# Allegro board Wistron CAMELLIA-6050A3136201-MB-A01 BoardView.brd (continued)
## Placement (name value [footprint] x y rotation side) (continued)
Q4751  PJX138K  [SOT563_160X120X060_6_050_P3]  203.67 70.64 180 bottom
Q4752  PJX138K  [SOT563_160X120X060_6_050_P3]  219.27 38.52 180 top
Q4754  LES_LBSS84LT1G_SOT23_3P  [TSSOT23_292X130X111_3_095]  250.85 48.88 0 top
Q4755  LES_LBSS84LT1G_SOT23_3P  [TSSOT23_292X130X111_3_095]  251.46 44.29 270 top
Q4756  TOSHIBA_SSM3K15AMFV_3P  [SOT723_120X080X055_3_040_P3]  39.27 35.63 270 bottom
Q4921  TOSHIBA_SSM3K15AMFV_3P_NP  [SOT723_120X080X055_3_040_NP]  107.97 43.37 0 top
Q7000  PJX138K  [SOT563_160X120X060_6_050_P3]  160.68 97.6 0 bottom
Q7001  PJS6416_6P  [SOT23_290X160X115_6_095]  199.42 91.02 270 bottom
Q7002  PJX138K  [SOT563_160X120X060_6_050_P3]  210.72 79.95 180 bottom
Q7003  PJX138K  [SOT563_160X120X060_6_050_P3]  211.99 89.35 180 bottom
Q7004  LN2312LT1G  [SOT23_290X130X110_3_095_P2]  214.78 88.97 0 bottom
Q7005  PJX138K  [SOT563_160X120X060_6_050_P3]  195.44 91.78 180 bottom
Q7006  TOSHIBA_SSM3K15AMFV_3P  [SOT723_120X080X055_3_040_P3]  216.05 91 90 top
Q7011  TOSHIBA_SSM3K15AMFV_3P  [SOT723_120X080X055_3_040_P3]  210.33 75.12 270 bottom
Q7151  ALPHA_AO6424L_TSOP_6P  [TSOP_290X160X125_6_095]  163.47 87.82 180 bottom
Q7153  ALPHA_AO6424L_TSOP_6P  [TSOP_290X160X125_6_095]  161.33 92.26 180 bottom
Q7154  LN2312LT1G  [SOT23_290X130X110_3_095_P2]  206.78 77.15 270 bottom
Q7159  EXCELLIANCE_MOS_EMB32N03K  [TSOT23_290X160X110_6_095]  167.03 42.99 0 top
Q7300  PJX138K  [SOT563_160X120X060_6_050_P3]  197.13 67.12 0 bottom
Q7306  PJX138K  [SOT563_160X120X060_6_050_P3]  211.05 77.28 0 bottom
Q7307  PJX138K  [SOT563_160X120X060_6_050_P3]  159.64 88.84 90 bottom
Q60000  AON6380  [MOSFET_500X600X100_8_127]  173.73 105.92 0 bottom
Q60001  AON6380  [MOSFET_500X600X100_8_127]  174.63 112.56 270 bottom
Q60002  AOS_AONR36368  [MOSFET_300X300X080_8_065]  157.12 114.2 0 bottom
Q60003  AOS_AONR36368  [MOSFET_300X300X080_8_065]  154.81 110.43 270 bottom
Q60010  SM3335PSQGC_TRG  [MOSFET_300X300X100_8_065]  252.12 96.15 180 top
Q60012  EMC_EMB07N03V  [MOSFET_300X300X090_8_065]  110.51 112.33 90 bottom
Q60032  L2N7002SWT1G  [SC70_200X125X100_3_065]  256.19 98.99 90 top
Q60033  LES_LBSS84LT1G_SOT23_3P  [TSSOT23_292X130X111_3_095]  248.46 97.68 90 top
Q60034  LES_LBSS84LT1G_SOT23_3P  [TSSOT23_292X130X111_3_095]  190.37 106.8 0 bottom
Q60035  L2N7002SWT1G  [SC70_200X125X100_3_065]  183.03 113.98 0 top
Q68000  YEL_LMBT3906LT1G_SOT23_3P  [TSSOT23_292X130X111_3_095]  209.55 115.97 90 bottom
Q68051  LMBT3904LT1G  [TSSOT23_292X130X111_3_096]  211.24 112.72 90 bottom
Q68054  L2N7002SWT1G  [SC70_200X125X100_3_065]  181 108.73 180 top
Q68098  L2N7002SWT1G  [SC70_200X125X100_3_065]  212.59 110.27 180 bottom
Q68100  SM3335PSQGC_TRG  [MOSFET_300X300X100_8_065]  252.5 91.94 90 top
Q68101  SM3335PSQGC_TRG  [MOSFET_300X300X100_8_065]  252.8 37.49 0 top
Q68102  NXP_PMBT3906YS_TSOT363_6P  [TSOT363_200X125X110_6_065_3]  243.99 28.64 270 top
Q68103  LES_LBSS84LT1G_SOT23_3P  [TSSOT23_292X130X111_3_095]  260.47 98.24 90 top
Q68104  LES_LBSS84LT1G_SOT23_3P  [TSSOT23_292X130X111_3_095]  254 41.19 180 top
Q68105  NXP_PMBT3906YS_TSOT363_6P  [TSOT363_200X125X110_6_065_3]  254.33 44.74 180 top
Q68106  SM3335PSQGC_TRG  [MOSFET_300X300X100_8_065]  266.11 83.15 270 top
Q68107  NXP_PMBT3906YS_TSOT363_6P  [TSOT363_200X125X110_6_065_3]  260.47 86.48 90 top
Q68108  LES_LBSS84LT1G_SOT23_3P  [TSSOT23_292X130X111_3_095]  254.28 84.9 90 top
Q68120  YEL_LMBT3906LT1G_SOT23_3P  [TSSOT23_292X130X111_3_095]  206.17 116.14 90 bottom
Q68121  YEL_LMBT3906LT1G_SOT23_3P  [TSSOT23_292X130X111_3_095]  206.19 112.84 90 bottom
R100  47_5%_1  [RSC_060X030X030_2]  241.37 30.88 180 top
R101  100K_5%_1  [RSC_060X030X030_2]  240.03 30.27 180 top
R103  100K_5%_1  [RSC_060X030X030_2]  240.03 29.66 180 top
R129  470K_1%_1  [RSC_060X030X030_2]  248.51 42.94 180 top
R200  short_0603_25  [RSC_160X080X080_2_25_SHORT]  55.44 10.38 270 bottom
R300  300_5%_1  [RSC_060X030X026_2]  246.99 40.07 180 top
R301  short_0201_5  [RSC_060X030X030_2_5_SHORT]  222.75 42.53 0 top
R302  300_5%_1  [RSC_060X030X026_2]  246.35 35.85 180 top
R303  100K_5%_1  [RSC_060X030X030_2]  242.39 50.87 0 bottom
R304  33_5%_1  [RSC_060X030X030_2]  221.33 36.01 180 top
R305  33_5%_1  [RSC_060X030X030_2]  221.48 36.62 180 top
R306  2.2K_5%_1  [RSC_060X030X030_2]  231.83 38.99 180 top
R307  2.2K_5%_1  [RSC_060X030X030_2]  231.82 39.61 180 top
R308  short_0201_5  [RSC_060X030X030_2_5_SHORT]  251.25 33.39 0 bottom
R309  34K_1%_2  [RSC_100X050X040_2]  248.11 36.84 0 top
R310  2.2K_5%_1  [RSC_060X030X030_2]  232.42 49.5 90 top
R311  2.2K_5%_1  [RSC_060X030X030_2]  233.04 49.37 90 top
R312  22_5%_1  [RSC_060X030X030_2]  216.13 47.94 270 top
R313  22_5%_1  [RSC_060X030X030_2]  224.63 47.94 270 top
R314  22_5%_1  [RSC_060X030X030_2]  222.75 47.94 270 top
R315  100K_5%_1  [RSC_060X030X030_2]  246.99 42.61 0 top
R316  4.7_5%_1  [RSC_060X030X030_2]  229.61 42.03 270 top
R317  100K_5%_1  [RSC_060X030X030_2]  250.72 46.47 90 top
R318  10K_5%_1  [RSC_060X030X030_2]  242.03 33.44 180 top
R319  short_0201_5  [RSC_060X030X030_2_5_SHORT]  253.62 31.82 0 bottom
R320  100K_5%_1  [RSC_060X030X030_2]  241.14 29.66 180 top
R321  20K_5%_1  [RSC_060X030X030_2]  242.21 47.61 180 top
R322  100K_5%_1  [RSC_060X030X030_2]  240.15 50.51 0 bottom
R323  short_0201_5  [RSC_060X030X030_2_5_SHORT]  253.62 32.42 0 bottom
R324  100K_5%_1  [RSC_060X030X030_2]  241.73 49.29 90 top
R325  10K_5%_1  [RSC_060X030X030_2]  249.86 46.27 0 top
R326  10K_5%_1  [RSC_060X030X030_2]  223.03 40.58 180 top
R327  470K_1%_2  [RSC_100X050X040_2]  238.68 25.36 180 top
R328  43_5%_1  [RSC_060X030X030_2]  237.61 49.37 90 top
R329  10K_5%_1  [RSC_060X030X030_2]  234.26 49.37 90 top
R330  short_0201_10  [RSC_060X030X030_2_10_SHORT]  233.65 49.37 90 top
R331  4.7K_5%_1  [RSC_060X030X030_2]  218.97 47.94 270 top
R332  short_0201_5  [RSC_060X030X030_2_5_SHORT]  239.82 48.6 270 top
R333  short_0201_5  [RSC_060X030X030_2_5_SHORT]  226.97 37.66 270 top
R334  100K_5%_1  [RSC_060X030X030_2]  241.09 49.29 90 top
R335  short_0201_5  [RSC_060X030X030_2_5_SHORT]  260.93 31.76 90 bottom
R336  15_5%_1  [RSC_060X030X030_2]  260.3 31.76 90 bottom
R337  15_5%_1  [RSC_060X030X030_2]  259.66 31.99 90 bottom
R338  15_5%_1  [RSC_060X030X030_2]  259.03 32.32 90 bottom
R339  15_5%_1  [RSC_060X030X030_2]  258.39 32.32 90 bottom
R340  short_0201_5  [RSC_060X030X030_2_5_SHORT]  252.5 32.53 0 bottom
R341  100K_5%_1  [RSC_060X030X030_2]  242.8 52.82 270 bottom
R342  10K_5%_1  [RSC_060X030X030_2]  249.86 46.98 180 top
R343  short_0402_15  [RSC_100X050X040_2_15_SHORT]  50.06 16.32 270 bottom
R344  3.3K_5%_1  [RSC_060X030X026_2]  230.7 26.41 315 top
R345  0_5%_1  [RSC_060X030X030_2]  229.89 27.37 135 top
R346  3.3K_5%_1  [RSC_060X030X026_2]  221.13 34.74 225 top
R347  short_0402_15  [RSC_100X050X040_2_15_SHORT]  226.49 39.44 0 top
R348  1K_5%_1  [RSC_060X030X030_2]  230.53 38.01 90 top
R349  1K_5%_1  [RSC_060X030X030_2]  244.47 47.84 90 top
R350  0_5%_1  [RSC_060X030X030_2]  239.14 30.88 180 top
R351  100K_5%_1  [RSC_060X030X030_2]  129.79 4.05 90 bottom
R352  100K_5%_1  [RSC_060X030X030_2]  240.48 34.06 270 top
R353  short_0201_10  [RSC_060X030X030_2_10_SHORT]  248.51 43.58 180 top
R354  10K_5%_1  [RSC_060X030X030_2]  240.1 49.9 0 bottom
R355  4.7K_5%_1  [RSC_060X030X030_2]  229.77 25.47 135 top
R356  1K_5%_1  [RSC_060X030X030_2]  236.04 31.05 0 top
R357  100K_5%_1  [RSC_060X030X030_2]  240.05 28.26 180 top
R358  short_0201_5  [RSC_060X030X030_2_5_SHORT]  250.97 32.58 0 bottom
R359  short_0402_15  [RSC_100X050X040_2_15_SHORT]  249.32 41.82 270 top
R360  short_0201_10  [RSC_060X030X030_2_10_SHORT]  240.05 53.91 180 bottom
R361  short_0201_10  [RSC_060X030X030_2_10_SHORT]  241.27 50.56 180 bottom
R362  short_0402_15  [RSC_100X050X040_2_15_SHORT]  48.26 16.32 270 bottom
R364  470_5%_1  [RSC_060X030X030_2]  47.49 16.07 270 bottom
R365  470_5%_1  [RSC_060X030X030_2]  46.89 16.07 270 bottom
R366  200_5%_2  [RSC_100X050X040_2]  45.74 16.07 180 bottom
R367  22_5%_1  [RSC_060X030X030_2]  225.85 47.94 90 top
R368  100K_5%_1  [RSC_060X030X030_2]  219.63 47.94 270 top
R369  100K_5%_1  [RSC_060X030X030_2]  223.36 47.94 270 top
R370  0_5%_1  [RSC_060X030X030_2]  222.15 47.94 270 top
R371  200_5%_2  [RSC_100X050X040_2]  51.2 19.37 270 bottom
R372  100K_5%_1  [RSC_060X030X030_2]  48.59 17.72 270 bottom
R373  short_0603_25  [RSC_160X080X080_2_25_SHORT]  223.57 60.31 270 bottom
R374  short_0201_5  [RSC_060X030X030_2_5_SHORT]  222.75 41.87 0 top
R375  1K_5%_1  [RSC_060X030X030_2]  235.66 29.45 0 top
R376  100K_5%_1  [RSC_060X030X030_2]  46.89 17.21 90 bottom
R377  short_0201_5  [RSC_060X030X030_2_5_SHORT]  226.36 37.66 90 top
R378  100K_5%_1  [RSC_060X030X030_2]  236.04 31.66 0 top
R379  2.2_5%_2  [RSC_100X050X040_2]  229.79 40.81 0 top
R380  1K_5%_1  [RSC_060X030X030_2]  232.2 35.27 180 top
R381  2.2_5%_3  [RSC_160X080X080_2]  246.46 38.57 90 top
R382  1K_5%_1  [RSC_060X030X030_2]  132.36 4.38 0 bottom
R383  0_5%_1  [RSC_060X030X030_2]  238.93 47.61 0 top
R384  short_0402_15  [RSC_100X050X040_2_15_SHORT]  247.83 37.76 180 top
R385  100K_5%_1  [RSC_060X030X030_2]  241.2 28.26 180 top
R386  0_5%_1  [RSC_060X030X030_2]  239.01 48.48 270 top
R387  100K_5%_1  [RSC_060X030X030_2]  224.81 38.55 0 top
R388  200_5%_2  [RSC_100X050X040_2]  49.17 16.32 270 bottom
R389  100K_5%_1  [RSC_060X030X030_2]  46.25 17.21 90 bottom
R390  33_5%_1  [RSC_060X030X030_2]  230.27 25.97 135 top
R391  10K_5%_1  [RSC_060X030X030_2]  231.8 49.49 90 top
R392  200_5%_2  [RSC_100X050X040_2]  44.09 16.07 0 bottom
R393  short_0402_15  [RSC_100X050X040_2_15_SHORT]  44.09 16.96 180 bottom
R394  10K_5%_1  [RSC_060X030X030_2]  231.19 49.49 90 top
R395  10_5%_1  [RSC_060X030X030_2]  257.63 33.11 90 bottom
R396  100K_5%_1  [RSC_060X030X030_2]  237 49.37 90 top
R397  2.2K_5%_1  [RSC_060X030X030_2]  231.75 38.01 90 top
R398  short_0201_5  [RSC_060X030X030_2_5_SHORT]  240.26 31.54 180 top
R399  200K_5%_1  [RSC_060X030X030_2]  46.76 21.02 270 bottom
R400  10K_5%_2  [RSC_100X050X040_2]  216.81 5.15 0 bottom
R401  short_0201_10  [RSC_060X030X030_2_10_SHORT]  108.38 7.41 0 top
R402  200K_5%_1  [RSC_060X030X030_2]  47.65 21.05 270 bottom
R403  100K_5%_2  [RSC_100X050X040_2]  49.55 21.68 270 bottom
R404  short_0402_15  [RSC_100X050X040_2_15_SHORT]  50.95 21.27 0 bottom
R405  short_0805_50  [RSC_200X125X115_2_50_SHORT]  228.09 38.5 90 top
R406  100K_5%_1  [RSC_060X030X030_2]  223.03 41.21 180 top
R407  short_0402_15  [RSC_100X050X040_2_15_SHORT]  215.54 5.02 90 bottom
R408  0_5%_1  [RSC_060X030X030_2]  47.39 21.91 0 bottom
R409  short_0201_10  [RSC_060X030X030_2_10_SHORT]  47.39 22.54 0 bottom
R410  short_0201_10  [RSC_060X030X030_2_10_SHORT]  45.49 21.02 270 bottom
R411  0_5%_1  [RSC_060X030X030_2]  46.12 21.02 270 bottom
R413  560_5%_2  [RSC_100X050X040_2]  269.39 100.65 270 top
R415  short_0201_5  [RSC_060X030X030_2_5_SHORT]  238.25 29.78 90 top
R417  10K_5%_1  [RSC_060X030X030_2]  250.75 34.43 90 bottom
R418  100K_5%_1  [RSC_060X030X030_2]  224.02 47.94 270 top
R419  33_5%_1  [RSC_060X030X030_2]  230.4 27.88 315 top
R420  short_0201_5  [RSC_060X030X030_2_5_SHORT]  229.61 45.02 0 top
R421  33_5%_1  [RSC_060X030X030_2]  219.81 35.4 135 top
R422  22_5%_1  [RSC_060X030X030_2]  220.24 47.94 270 top
R423  1M_5%_1  [RSC_060X030X030_2]  259.72 3.09 0 bottom
R424  100_5%_2  [RSC_100X050X040_2]  231.29 57.22 180 top
R425  22_5%_1  [RSC_060X030X030_2]  226.46 47.94 270 top
R426  10K_5%_1  [RSC_060X030X030_2]  239.42 33.97 270 top
R428  0_5%_1  [RSC_060X030X030_2]  25.83 19.5 0 top
R430  100K_1%_1  [RSC_060X030X030_2]  244.12 33.16 270 top
R431  806K_1%_2  [RSC_100X050X040_2]  243.23 34.81 0 top
R432  100K_1%_1  [RSC_060X030X030_2]  242.9 33.16 270 top
R433  short_0201_10  [RSC_060X030X030_2_10_SHORT]  231.04 42.18 90 top
R434  short_0201_10  [RSC_060X030X030_2_10_SHORT]  223.92 40.07 270 top
R435  560_5%_2  [RSC_100X050X040_2]  268.5 100.9 270 top
R439  4.7_5%_1  [RSC_060X030X030_2]  228.5 45.02 0 top
R440  4.7_5%_1  [RSC_060X030X030_2]  229.61 43.14 270 top
R441  4.7_5%_1  [RSC_060X030X030_2]  223.52 43.58 90 top
R442  22_5%_1  [RSC_060X030X030_2]  218.34 47.94 270 top
R443  300_5%_1  [RSC_060X030X026_2]  246.99 40.71 180 top
R444  300_5%_1  [RSC_060X030X026_2]  245.43 35.19 90 top
R445  1M_5%_2  [RSC_100X050X040_2]  216.81 3.75 180 bottom
R449  22K_5%_2  [RSC_100X050X040_2]  237.64 28.77 0 top
R500  100K_5%_2  [RSC_100X050X040_2]  28.47 37.02 180 top
R501  100K_1%_2  [RSC_100X050X040_2]  17.57 34.4 270 top
R502  1K_5%_2  [RSC_100X050X040_2]  28.47 36.13 180 top
R503  short_0402_15  [RSC_100X050X040_2_15_SHORT]  16.68 34.4 270 top
R504  33_5%_1  [RSC_060X030X030_2]  26.97 37.98 0 top
R505  0_5%_1  [RSC_060X030X030_2]  26.97 37.12 0 top
R506  100K_5%_2  [RSC_100X050X040_2]  17.14 43.71 0 top
R507  1K_5%_1  [RSC_060X030X030_2]  17.75 45.91 270 top
R508  10K_5%_2  [RSC_100X050X040_2]  13.36 46.04 0 top
R509  short_0805_40_nsp  [RSC_200X125X115_2_40_SHORT_NSP]  8.79 44.77 90 top
R510  short_0805_40_nsp  [RSC_200X125X115_2_40_SHORT_NSP]  7.18 44.77 90 top
R511  2.2K_5%_2  [RSC_100X050X040_2]  22.96 46.01 180 top
R512  short_0805_50  [RSC_200X125X115_2_50_SHORT]  12.9 36.21 0 top
R513  Short_0805_50_NSP  [RSC_200X125X115_2_50_SHORT_NSP]  43.96 36.13 180 top
R514  short_0805_50  [RSC_200X125X115_2_50_SHORT]  28.47 45.66 180 top
R515  short_0201_10  [RSC_060X030X030_2_10_SHORT]  19.33 36.59 0 top
R516  100K_5%_2  [RSC_100X050X040_2]  26.67 35.78 0 top
R517  short_0402_15  [RSC_100X050X040_2_15_SHORT]  11.45 43.4 90 top
R518  100K_5%_2  [RSC_100X050X040_2]  13.24 44.79 90 top
R519  200K_5%_2  [RSC_100X050X040_2]  11.22 42.15 0 top
R520  short_0603_25  [RSC_160X080X080_2_25_SHORT]  14.86 43.88 0 top
R521  short_0603_25  [RSC_160X080X080_2_25_SHORT]  14.26 42.11 270 top
R550  short_0603_25  [RSC_160X080X080_2_25_SHORT]  5.93 40.26 180 top
R551  short_0603_25  [RSC_160X080X080_2_25_SHORT]  5.93 36.3 180 top
R566  short_0603_25  [RSC_160X080X080_2_25_SHORT]  5.93 37.44 180 top
R567  short_0603_25  [RSC_160X080X080_2_25_SHORT]  5.93 38.99 180 top
R906  51.1K_1%_2  [RSC_100X050X040_2]  245.41 37.43 270 top
R1000  10K_5%_2  [RSC_100X050X040_2]  236.39 28.08 270 top
R1001  100K_5%_2  [RSC_100X050X040_2]  236.39 26.46 270 top
R1002  10K_5%_2  [RSC_100X050X040_2]  140.53 5.91 180 top
R1003  10K_5%_2  [RSC_100X050X040_2]  140.53 7.76 180 top
R1004  100K_5%_2  [RSC_100X050X040_2]  140.53 6.8 0 top
R1005  short_0402_15  [RSC_100X050X040_2_15_SHORT]  140.53 8.65 0 top
R1006  short_0402_15  [RSC_100X050X040_2_15_SHORT]  135.53 8.32 270 top
R1007  10K_5%_1  [RSC_060X030X030_2]  215.16 47.77 0 top
R1008  1M_5%_1  [RSC_060X030X030_2]  262.69 8.31 180 bottom
R1009  10M_5%_1  [RSC_060X030X030_2]  260.82 3.09 0 bottom
R1010  short_0402_15  [RSC_100X050X040_2_15_SHORT]  239.95 26.63 90 top
R1011  short_0201_10  [RSC_060X030X030_2_10_SHORT]  24.15 7.61 270 bottom
R1012  100K_5%_1  [RSC_060X030X030_2]  237.18 26.41 90 top
R1013  short_0402_15  [RSC_100X050X040_2_15_SHORT]  134.74 9.59 0 top
R1014  10K_5%_2  [RSC_100X050X040_2]  215.29 102.3 90 bottom
R1015  220K_1%_2  [RSC_100X050X040_2]  214.02 102.81 180 bottom
R1016  110K_1%_2  [RSC_100X050X040_2]  214.02 101.92 0 bottom
R1017  10K_5%_2  [RSC_100X050X040_2]  214.3 98.11 0 bottom
R1018  100K_5%_1  [RSC_060X030X030_2]  246.53 46.17 0 top
R1019  10K_5%_1  [RSC_060X030X030_2]  221.89 58.23 270 top
R1021  10K_5%_2  [RSC_100X050X040_2]  134.29 8.68 180 top
R1300  100K_5%_1  [RSC_060X030X030_2]  188.82 70.8 180 top
R1301  10K_5%_2  [RSC_100X050X040_2]  54.86 22.34 0 bottom
R1302  150_1%_2  [RSC_100X050X040_2]  73.94 38.04 0 bottom
R1303  short_0402_15  [RSC_100X050X040_2_15_SHORT]  51.08 27.24 180 bottom
R1304  100K_5%_2  [RSC_100X050X040_2]  55.37 24.39 90 top
R1305  100K_5%_2  [RSC_100X050X040_2]  51.08 26.35 0 bottom
R1306  10K_5%_2  [RSC_100X050X040_2]  61.24 29.53 270 bottom
R1307  100K_5%_2  [RSC_100X050X040_2]  58.04 29.15 180 bottom
R1308  short_0402_15  [RSC_100X050X040_2_15_SHORT]  56.38 29.12 180 bottom
R1309  20K_5%_1  [RSC_060X030X030_2]  59.97 23.26 90 bottom
R1310  short_0201_5  [RSC_060X030X030_2_5_SHORT]  60.91 27.6 0 bottom
R1312  22_1%_1  [RSC_060X030X026_2]  193.32 60.47 90 bottom
R1313  22_1%_1  [RSC_060X030X026_2]  60.93 22.34 180 bottom
R1314  22_1%_1  [RSC_060X030X026_2]  61.19 23.26 270 bottom
R1315  short_0805_50  [RSC_200X125X115_2_50_SHORT]  59.69 35.24 0 bottom
R1316  22_1%_1  [RSC_060X030X026_2]  61.13 24.98 270 bottom
R1317  short_0402_15  [RSC_100X050X040_2_15_SHORT]  60.6 21.15 90 bottom
R1318  short_0201_10  [RSC_060X030X030_2_10_SHORT]  60.47 20.04 0 bottom
R1319  short_0201_10  [RSC_060X030X030_2_10_SHORT]  59.61 19.75 270 bottom
R1320  short_0201_10  [RSC_060X030X030_2_10_SHORT]  73.56 34.86 0 bottom
R1321  short_0201_10  [RSC_060X030X030_2_10_SHORT]  73.56 34.23 0 bottom
R1322  short_0201_10  [RSC_060X030X030_2_10_SHORT]  73.56 33.34 0 bottom
R1323  short_0201_10  [RSC_060X030X030_2_10_SHORT]  73.56 32.7 0 bottom
R1324  short_0201_10  [RSC_060X030X030_2_10_SHORT]  73.56 31.82 0 bottom
R1325  short_0201_10  [RSC_060X030X030_2_10_SHORT]  73.56 31.18 0 bottom
R1326  short_0201_10  [RSC_060X030X030_2_10_SHORT]  72.21 23.18 90 bottom
R1327  short_0201_10  [RSC_060X030X030_2_10_SHORT]  72.82 23.18 90 bottom
R1328  short_0201_10  [RSC_060X030X030_2_10_SHORT]  73.43 23 90 bottom
R1329  short_0201_10  [RSC_060X030X030_2_10_SHORT]  74.04 23 90 bottom
R1332  71.5K_1%_2  [RSC_100X050X040_2]  59.71 21.15 90 bottom
R1333  4.7K_5%_1  [RSC_060X030X030_2]  60.58 23.26 270 bottom
R1334  short_0201_10  [RSC_060X030X030_2_10_SHORT]  74.65 23 90 bottom
R1335  short_0201_10  [RSC_060X030X030_2_10_SHORT]  75.25 23 90 bottom
R1336  10K_5%_2  [RSC_100X050X040_2]  180.26 84.47 0 bottom
R1337  0_5%_2  [RSC_100X050X040_2]  60.6 33.97 0 bottom
R1338  short_0201_10  [RSC_060X030X030_2_10_SHORT]  74.34 26.84 0 bottom
R1339  short_0201_10  [RSC_060X030X030_2_10_SHORT]  74.34 26.23 0 bottom
R1342  100K_5%_2  [RSC_100X050X040_2]  49.81 35.12 270 bottom
R1343  220K_5%_2  [RSC_100X050X040_2]  52.73 31.18 90 bottom
R1344  4.7K_5%_1  [RSC_060X030X030_2]  193.32 62.17 90 bottom
R1345  20K_5%_1  [RSC_060X030X030_2]  193.95 62.17 270 bottom
R1346  100K_5%_2  [RSC_100X050X040_2]  60.86 30.8 0 bottom
R1347  short_0402_15  [RSC_100X050X040_2_15_SHORT]  53.21 22.34 0 bottom
R1349  short_0402_15  [RSC_100X050X040_2_15_SHORT]  51.08 29.66 0 bottom
R1351  short_0402_15  [RSC_100X050X040_2_15_SHORT]  51.78 24.44 90 bottom
R1400  100K_5%_1  [RSC_060X030X030_2]  197.76 50.74 90 bottom
R1401  20K_5%_1  [RSC_060X030X030_2]  208 62.07 90 bottom
R1402  0_5%_2  [RSC_100X050X040_2]  206.65 63.31 90 bottom
R1403  short_0805_50  [RSC_200X125X115_2_50_SHORT]  216.56 61.03 90 top
R1404  10K_5%_1  [RSC_060X030X030_2]  200.17 61.28 180 top
R1405  10_5%_1  [RSC_060X030X030_2]  201.83 63.44 90 bottom
R1406  10_5%_1  [RSC_060X030X030_2]  202.46 63.44 90 bottom
R1407  0_5%_2  [RSC_100X050X040_2]  205.76 63.31 90 bottom
R1408  100K_5%_1  [RSC_060X030X030_2]  205 52.9 180 top
R1409  0_5%_2  [RSC_100X050X040_2]  208.3 66.11 0 bottom
R1410  100K_5%_1  [RSC_060X030X030_2]  209.38 56.18 270 top
R1411  0_5%_1  [RSC_060X030X030_2]  210.02 56.19 90 top
R1412  short_0201_10  [RSC_060X030X030_2_10_SHORT]  213.64 55.82 180 top
R1413  0_5%_1  [RSC_060X030X030_2]  203.86 52.9 180 top
R1414  short_0201_10  [RSC_060X030X030_2_10_SHORT]  215.32 63.19 270 bottom
R1417  100K_5%_2  [RSC_100X050X040_2]  215.8 65.85 180 bottom
R1451  47K_5%_1  [RSC_060X030X030_2]  269.23 45.32 90 top
R1452  100K_5%_1  [RSC_060X030X030_2]  269.85 47.6 90 top
R1952  1K_5%_2  [RSC_100X050X040_2]  259.99 10.48 0 top
R1953  short_0805_50  [RSC_200X125X115_2_50_SHORT]  265.53 18.71 270 top
R1954  100K_5%_2  [RSC_100X050X040_2]  267.74 12.13 270 top
R2200  100K_5%_1  [RSC_060X030X030_2]  234.69 7.94 0 top
R2401  short_0402_15  [RSC_100X050X040_2_15_SHORT]  257.6 33.33 270 top
R2402  short_0402_15  [RSC_100X050X040_2_15_SHORT]  255.23 32.92 0 top
R2418  10K_5%_2  [RSC_100X050X040_2]  266.89 22.25 0 top
R2420  0_5%_2  [RSC_100X050X040_2]  255.23 30.99 0 top
R2421  100K_5%_2  [RSC_100X050X040_2]  262.23 20.69 270 top
R2422  100K_5%_2  [RSC_100X050X040_2]  263.8 33.21 90 bottom
R2423  100K_5%_2  [RSC_100X050X040_2]  249.55 26.51 180 top
R2424  100K_5%_2  [RSC_100X050X040_2]  249.55 27.42 180 top
R2425  100K_5%_2  [RSC_100X050X040_2]  249.56 24.67 180 top
R2427  0_5%_2  [RSC_100X050X040_2]  255.22 28.49 0 top
R2428  100K_5%_2  [RSC_100X050X040_2]  249.56 25.59 180 top
R2441  4.7K_5%_2  [RSC_100X050X040_2]  262.91 33.21 270 bottom
R2449  0_5%_2  [RSC_100X050X040_2]  266.89 23.17 0 top
R2456  short_0805_50  [RSC_200X125X115_2_50_SHORT]  261.77 18.86 180 top
R2457  1K_1%_2  [RSC_100X050X040_2]  250.9 21.93 0 top
R2458  1K_1%_2  [RSC_100X050X040_2]  250.9 22.85 180 top
R2463  51K_1%_2  [RSC_100X050X040_2]  255.77 20.83 180 top
R2464  357K_1%_2  [RSC_100X050X040_2]  257.83 20.78 0 top
R2465  76.8K_1%_2  [RSC_100X050X040_2]  257.83 19.88 0 top
R2466  127K_1%  [RSC_100X050X040_2]  255.77 19.93 180 top
R2469  short_0603_25  [RSC_160X080X080_2_25_SHORT]  269.36 33.49 0 top
R2500  17.8K_1%_2  [RSC_100X050X040_2]  25.88 27.12 270 top
R2501  33.2K_1%_2  [RSC_100X050X040_2]  25.88 25.47 270 top
R2502  10K_5%_2  [RSC_100X050X040_2]  27 31.18 90 top
R2503  0_5%_2  [RSC_100X050X040_2]  27.89 31.18 270 top
R2513  short_0201_5  [RSC_060X030X030_2_5_SHORT]  245.44 42.43 0 top
R2600  10K_5%_2  [RSC_100X050X040_2]  256.64 40.81 180 top
R2601  220K_5%_2  [RSC_100X050X040_2]  258.26 42.25 0 top
R2602  200K_5%_2  [RSC_100X050X040_2]  257.06 46.42 0 top
R2603  14.3K_1%_2  [RSC_100X050X040_2]  265.55 96.53 0 top
R2604  47K_5%_2  [RSC_100X050X040_2]  266.44 97.78 270 top
R2605  220K_1%_1  [RSC_060X030X026_2]  278.45 76.76 90 bottom
R2606  300K_5%_2  [RSC_100X050X040_2]  254.96 47.36 270 top
R2607  220K_1%_1  [RSC_060X030X026_2]  276.04 68.54 90 bottom
R2608  220K_1%_1  [RSC_060X030X026_2]  276.04 67.43 270 bottom
R2609  220K_1%_1  [RSC_060X030X026_2]  277.41 62.37 90 top
R2610  10K_5%_2  [RSC_100X050X040_2]  268.63 86.37 90 top
R2611  20K_1%_2  [RSC_100X050X040_2]  263.22 95.11 180 top
R2612  10K_5%_2  [RSC_100X050X040_2]  263.22 96.03 0 top
R2613  200K_5%_2  [RSC_100X050X040_2]  261.59 95.11 0 top
R2614  300K_5%_2  [RSC_100X050X040_2]  261.59 96.03 0 top
R2615  100K_5%_2  [RSC_100X050X040_2]  265.2 97.78 90 top
R2616  220K_1%_1  [RSC_060X030X026_2]  278.45 75.64 270 bottom
R2617  14.3K_1%_2  [RSC_100X050X040_2]  263.78 42.28 180 top
R2618  1M_5%_2  [RSC_100X050X040_2]  267.71 97.59 0 top
R2619  20K_1%_2  [RSC_100X050X040_2]  258.66 46.42 180 top
R2620  47K_5%_2  [RSC_100X050X040_2]  265.15 42.05 270 top
R2621  10K_5%_2  [RSC_100X050X040_2]  258.62 47.33 0 top
R2622  220K_1%_1  [RSC_060X030X026_2]  278.45 80.77 270 bottom
R2623  220K_1%_1  [RSC_060X030X026_2]  277.41 63.49 270 top
R2624  220K_1%_1  [RSC_060X030X026_2]  278.45 81.89 90 bottom
R2625  Short_0805_50_NSP  [RSC_200X125X115_2_50_SHORT_NSP]  260.91 44.16 0 top
R2626  short_0402_15  [RSC_100X050X040_2_15_SHORT]  259.69 34.99 270 top
R2627  100K_5%_2  [RSC_100X050X040_2]  258.06 49.09 90 top
R2628  1M_5%_2  [RSC_100X050X040_2]  267.79 40.43 90 top
R2629  220K_1%_1  [RSC_060X030X026_2]  278.15 75.64 90 top
R2630  220K_1%_1  [RSC_060X030X026_2]  278.15 76.76 270 top
R2631  220K_1%_1  [RSC_060X030X026_2]  278.15 80.77 90 top
R2632  220K_1%_1  [RSC_060X030X026_2]  278.15 81.89 270 top
R2633  100K_5%_2  [RSC_100X050X040_2]  256.69 33.16 270 top
R2634  100K_5%_2  [RSC_100X050X040_2]  253.22 32.92 180 top
R2635  220K_5%_2  [RSC_100X050X040_2]  269.54 86.37 90 top
R2638  Short_0805_50_NSP  [RSC_200X125X115_2_50_SHORT_NSP]  268.18 89.34 90 top
R2639  Short_0805_50_NSP  [RSC_200X125X115_2_50_SHORT_NSP]  269.81 89.34 90 top
R2640  220K_1%_1  [RSC_060X030X026_2]  276.65 63.49 90 bottom
R2641  220K_1%_1  [RSC_060X030X026_2]  276.65 62.37 270 bottom
R2642  220K_1%_1  [RSC_060X030X026_2]  276.04 67.43 90 top
R2643  220K_1%_1  [RSC_060X030X026_2]  276.04 68.54 270 top
R2647  Short_0805_50_NSP  [RSC_200X125X115_2_50_SHORT_NSP]  271.43 89.34 90 top
R2655  short_0402_15  [RSC_100X050X040_2_15_SHORT]  254.07 20.68 270 top
R2656  short_0402_15  [RSC_100X050X040_2_15_SHORT]  253.16 20.68 270 top
R2657  short_0402_15  [RSC_100X050X040_2_15_SHORT]  253.15 29.16 180 top
R2658  short_0402_15  [RSC_100X050X040_2_15_SHORT]  253.15 30.08 180 top
R2660  short_0402_15  [RSC_100X050X040_2_15_SHORT]  258.44 35.63 0 top
R2669  Short_0805_50_NSP  [RSC_200X125X115_2_50_SHORT_NSP]  260.91 42.56 0 top
R2671  Short_0805_50_NSP  [RSC_200X125X115_2_50_SHORT_NSP]  260.91 45.79 0 top
R2684  short_0402_15  [RSC_100X050X040_2_15_SHORT]  257.2 34.94 270 top
R2700  100_1%_1  [RSC_060X030X030_2]  253.34 65.95 0 bottom
R2701  100K_5%_1  [RSC_060X030X030_2]  247.34 74.72 270 top
R2702  short_0201_5  [RSC_060X030X030_2_5_SHORT]  253.54 73.7 270 top
R2703  0_5%_1  [RSC_060X030X030_2]  250.36 74.18 0 top
R2704  short_0201_5  [RSC_060X030X030_2_5_SHORT]  252.9 73.7 270 top
R2705  0_5%_1  [RSC_060X030X030_2]  247.85 70.65 90 top
R2706  100K_5%_1  [RSC_060X030X030_2]  246.15 71.39 0 top
R2708  3.01K_1%_1  [RSC_060X030X030_2]  257.83 60.9 90 bottom
R2709  short_0201_10  [RSC_060X030X030_2_10_SHORT]  248.41 76.27 180 top
R2710  10K_5%_1  [RSC_060X030X030_2]  253.31 71.97 270 top
R2711  10K_5%_1  [RSC_060X030X030_2]  250.06 68.87 180 top
R2712  10K_5%_1  [RSC_060X030X030_2]  247.16 73.6 90 top
R2713  2.2_1%_1  [RSC_060X030X026_2]  266.85 58.43 180 top
R2714  2.2_1%_1  [RSC_060X030X026_2]  266.85 60.26 180 top
R2715  2.2_1%_1  [RSC_060X030X026_2]  266.85 59.04 180 top
R2716  2.2_1%_1  [RSC_060X030X026_2]  266.85 59.65 180 top
R2717  2.2_1%_1  [RSC_060X030X026_2]  266.85 61.48 180 top
R2718  2.2_1%_1  [RSC_060X030X026_2]  266.85 62.7 180 top
R2719  2.2_1%_1  [RSC_060X030X026_2]  266.85 62.09 180 top
R2720  2.2_1%_1  [RSC_060X030X026_2]  266.85 60.87 180 top
R2721  200_1%_1  [RSC_060X030X030_2]  263.19 59.35 180 bottom
R2722  short_0201_10  [RSC_060X030X030_2_10_SHORT]  250.06 69.48 0 top
R2723  200_1%_1  [RSC_060X030X030_2]  263.19 60.57 180 bottom
R2724  2.2K_5%_1  [RSC_060X030X030_2]  252.07 73.7 90 top
R2725  2.2K_5%_1  [RSC_060X030X030_2]  252.07 71.97 270 top
R2726  10K_5%_1  [RSC_060X030X030_2]  253.18 78.32 0 top
R2727  short_0201_10  [RSC_060X030X030_2_10_SHORT]  253.34 64.73 0 bottom
R2728  10K_5%_1  [RSC_060X030X030_2]  250.06 67.65 180 top
R2729  10K_5%_1  [RSC_060X030X030_2]  253.18 77.64 0 top
R2730  10K_5%_1  [RSC_060X030X030_2]  250.06 68.26 180 top
R2731  100K_5%_1  [RSC_060X030X030_2]  253.34 65.34 0 bottom
R2732  100K_5%_1  [RSC_060X030X030_2]  252.32 75.94 270 top
R2733  100K_5%_1  [RSC_060X030X030_2]  248.08 73.6 180 top
R2734  100K_5%_1  [RSC_060X030X030_2]  254.3 75.94 90 top
R2735  100K_5%_1  [RSC_060X030X030_2]  254.89 71.97 270 top
R2736  100K_5%_1  [RSC_060X030X030_2]  254.89 73.7 90 top
R2737  100K_5%_1  [RSC_060X030X030_2]  248.21 68.26 0 top
R2738  100K_5%_1  [RSC_060X030X030_2]  251.23 73.67 90 top
R2739  100K_5%_1  [RSC_060X030X030_2]  248.21 68.87 0 top
R2740  100K_5%_1  [RSC_060X030X030_2]  250.36 72.81 0 top
R2741  100K_5%_1  [RSC_060X030X030_2]  251.23 72 270 top
R2742  short_0201_5  [RSC_060X030X030_2_5_SHORT]  270.07 76.95 90 top
R2743  10K_5%_1  [RSC_060X030X030_2]  251.74 59.25 0 bottom
R2744  10K_5%_1  [RSC_060X030X030_2]  251.74 59.88 0 bottom
R2745  10K_5%_1  [RSC_060X030X030_2]  251.74 58.61 0 bottom
R2746  10K_5%_1  [RSC_060X030X030_2]  251.74 60.77 0 bottom
R2747  47_5%_1  [RSC_060X030X030_2]  263.45 55.03 0 bottom
R2748  47_5%_1  [RSC_060X030X030_2]  263.45 55.67 0 bottom
R2749  100K_5%_1  [RSC_060X030X030_2]  269.44 76.95 90 top
R2750  4.75K_0.5%_1  [RSC_060X030X026_2]  259.23 68.06 0 bottom
R2751  3.3K_5%_2  [RSC_100X050X040_2]  247.55 54.93 90 top
R2752  2.2K_5%_2  [RSC_100X050X040_2]  245.26 66.11 0 top
R2753  2.2K_5%_2  [RSC_100X050X040_2]  243.61 66.11 0 top
R2754  3.3K_5%_2  [RSC_100X050X040_2]  241.96 66.11 180 top
R2755  0_5%_2  [RSC_100X050X040_2]  271.36 72.23 180 top
R2756  short_0402_15  [RSC_100X050X040_2_15_SHORT]  271.36 73.12 180 top
R2757  0_5%_3  [RSC_160X080X055_2]  265.88 79.16 180 top
R2758  short_0603_25  [RSC_160X080X080_2_25_SHORT]  265.88 77.76 180 top
R2759  0_5%_1  [RSC_060X030X030_2]  248.46 70.65 90 top
R2760  10K_5%_1  [RSC_060X030X030_2]  248.21 69.79 0 top
R2761  0_5%_1  [RSC_060X030X030_2]  253.08 76.04 270 top
R2762  0_5%_1  [RSC_060X030X030_2]  253.69 75.94 270 top
R2763  0_5%_1  [RSC_060X030X030_2]  251.71 75.94 270 top
R2764  0_5%_1  [RSC_060X030X030_2]  251.08 75.94 270 top
R2765  2.2_1%_1  [RSC_060X030X026_2]  266.85 65.75 180 top
R2766  2.2_1%_1  [RSC_060X030X026_2]  266.85 66.36 180 top
R2767  2.2_1%_1  [RSC_060X030X026_2]  266.85 66.97 180 top
R2768  2.2_1%_1  [RSC_060X030X026_2]  266.85 67.58 180 top
R2769  2.2_1%_1  [RSC_060X030X026_2]  266.85 65.14 180 top
R2770  2.2_1%_1  [RSC_060X030X026_2]  266.85 64.53 180 top
R2771  2.2_1%_1  [RSC_060X030X026_2]  266.85 63.92 180 top
R2772  2.2_1%_1  [RSC_060X030X026_2]  266.85 63.31 180 top
R2773  short_0402_15  [RSC_100X050X040_2_15_SHORT]  255.75 73.9 270 top
R2774  short_0402_15  [RSC_100X050X040_2_15_SHORT]  256.64 73.9 270 top
R2775  10K_5%_1  [RSC_060X030X030_2]  250.34 73.47 0 top
R3000  short_0805_50  [RSC_200X125X115_2_50_SHORT]  22.37 26.61 180 top
R3001  1K_5%_2  [RSC_100X050X040_2]  224.94 105.48 270 top
R3002  short_0402_15  [RSC_100X050X040_2_15_SHORT]  25.35 11.55 270 top
R3003  100K_5%_2  [RSC_100X050X040_2]  53.08 8.54 90 top
R3004  short_0402_15  [RSC_100X050X040_2_15_SHORT]  24.91 20.26 0 top
R3005  10K_5%_2  [RSC_100X050X040_2]  19.65 11 270 top
R3006  100K_5%_2  [RSC_100X050X040_2]  24.79 17.29 270 top
R3007  220K_5%_1  [RSC_060X030X030_2]  224.05 103.57 270 top
R3008  100K_5%_2  [RSC_100X050X040_2]  21.74 21.66 270 top
R3009  1K_5%_2  [RSC_100X050X040_2]  21.74 23.81 90 top
R3010  2.2K_5%_1  [RSC_060X030X030_2]  25.4 14.06 270 top
R3012  100K_5%_2  [RSC_100X050X040_2]  220.11 102.55 90 bottom
R3013  2.2K_5%_1  [RSC_060X030X030_2]  25.42 15.61 90 top
R3014  short_0402_15  [RSC_100X050X040_2_15_SHORT]  218.59 96.46 90 bottom
R3015  1M_5%_2  [RSC_100X050X040_2]  25.3 23.81 90 top
R3016  short_0402_15  [RSC_100X050X040_2_15_SHORT]  218.89 99.66 90 bottom
R3017  short_0402_15  [RSC_100X050X040_2_15_SHORT]  23.64 19.37 90 top
R3018  10K_5%_1  [RSC_060X030X030_2]  25.4 12.92 270 top
R3020  short_0402_15  [RSC_100X050X040_2_15_SHORT]  24.41 23.81 90 top
R3021  100K_5%_2  [RSC_100X050X040_2]  22.63 23.81 270 top
R3022  0_5%_2  [RSC_100X050X040_2]  23.52 23.81 90 top
R3023  100K_5%_2  [RSC_100X050X040_2]  221.13 71.06 0 bottom
R3024  short_0402_15  [RSC_100X050X040_2_15_SHORT]  22.76 19.37 90 top
R3026  470K_5%_2  [RSC_100X050X040_2]  21.87 19.37 270 top
R3027  100K_5%_2  [RSC_100X050X040_2]  19.83 26.74 270 top
R3028  100K_5%_2  [RSC_100X050X040_2]  19.83 24.45 180 top
R3029  100_5%_2  [RSC_100X050X040_2]  53.98 8.54 90 top
R3030  10K_5%_2  [RSC_100X050X040_2]  20.89 9.97 180 top
R3031  150_1%_2  [RSC_100X050X040_2]  20.72 15.9 270 top
R3033  220K_5%_1  [RSC_060X030X030_2]  224.18 101.03 270 top
R3034  100K_5%_1  [RSC_060X030X030_2]  223.42 103.57 90 top
R3035  100K_5%_2  [RSC_100X050X040_2]  221.66 99.35 90 bottom
R3036  100K_5%_2  [RSC_100X050X040_2]  221.89 96.71 180 bottom
R3150  2K_5%_2  [RSC_100X050X040_2]  273.63 96 0 bottom
R3151  2K_5%_2  [RSC_100X050X040_2]  273.35 93.4 0 bottom
R3300  4.7K_5%_2  [RSC_100X050X040_2]  233.78 95.8 90 top
R3301  4.7K_5%_2  [RSC_100X050X040_2]  232.84 95.8 90 top
R3302  100K_5%_2  [RSC_100X050X040_2]  235.98 98.33 0 top
R3303  4.7K_5%_2  [RSC_100X050X040_2]  250.4 88.37 0 top
R3304  100K_5%_2  [RSC_100X050X040_2]  234.38 98.33 180 top
R3305  4.7K_5%_2  [RSC_100X050X040_2]  250.4 87.46 0 top
R3306  100K_5%_2  [RSC_100X050X040_2]  235.98 97.44 180 top
R3307  100K_5%_2  [RSC_100X050X040_2]  234.38 97.44 0 top
R3308  1M_5%_2  [RSC_100X050X040_2]  236.88 84.22 0 top
R3309  4.7K_5%_2  [RSC_100X050X040_2]  249.47 92.1 0 top
R3310  4.7K_5%_2  [RSC_100X050X040_2]  247.21 92.1 0 top
R3311  4.7K_5%_2  [RSC_100X050X040_2]  252.16 88.41 180 top
R3312  4.7K_5%_2  [RSC_100X050X040_2]  252.16 87.5 180 top
R3314  1M_5%_2  [RSC_100X050X040_2]  246.58 95.39 0 top
R3319  4.7K_5%_2  [RSC_100X050X040_2]  251.93 89.33 0 top
R3320  4.7K_5%_2  [RSC_100X050X040_2]  249.9 89.33 0 top
R3322  4.7K_5%_2  [RSC_100X050X040_2]  243.74 98.64 90 top
R3323  4.7K_5%_2  [RSC_100X050X040_2]  242.82 97.22 90 top
R3324  5.1K_1%_2  [RSC_100X050X040_2]  245.27 84.64 180 top
R3339  4.7K_5%_2  [RSC_100X050X040_2]  243.74 97.04 90 top
R3340  4.7K_5%_2  [RSC_100X050X040_2]  236.88 82.39 0 top
R3341  4.7K_5%_2  [RSC_100X050X040_2]  238.14 97.94 90 top
R3342  4.7K_5%_2  [RSC_100X050X040_2]  237.25 97.94 90 top
R3355  4.7K_5%_2  [RSC_100X050X040_2]  246.58 96.31 0 top
R3356  4.7K_5%_2  [RSC_100X050X040_2]  236.88 83.3 0 top
R3501  0_5%_1  [RSC_060X030X030_2]  223.62 61.03 0 top
R3502  4.7K_5%_1  [RSC_060X030X030_2]  223.62 61.66 180 top
R3503  4.7K_5%_1  [RSC_060X030X030_2]  225.32 61.51 270 top
R3504  short_0201_5  [RSC_060X030X030_2_5_SHORT]  221.63 55.94 180 top
R3505  short_0201_5  [RSC_060X030X030_2_5_SHORT]  221.61 55.1 180 top
R3516  10K_5%_1  [RSC_060X030X030_2]  224.13 53.33 90 top
R3517  150K_1%  [RSC_060X030X026_2]  221 53.91 90 top
R3541  10K_5%_1  [RSC_060X030X030_2]  219.61 55.06 90 top
R3542  10K_5%_1  [RSC_060X030X030_2]  216.81 56.2 270 top
R3543  51K_1%_1  [RSC_060X030X030_2]  216.81 55.06 270 top
R3800  20K_5%_1  [RSC_060X030X030_2]  197.48 80.46 180 top
R3801  20K_5%_1  [RSC_060X030X030_2]  196.76 72.57 180 top
R3802  0_5%_1  [RSC_060X030X030_2]  196.76 71.94 0 top
R3803  0_5%_1  [RSC_060X030X030_2]  196.76 73.21 0 top
R3804  0_5%_1  [RSC_060X030X030_2]  198.6 80.96 0 top
R3805  0_5%_1  [RSC_060X030X030_2]  197.48 81.93 0 top
R3806  0_5%_1  [RSC_060X030X030_2]  197 83.61 90 top
R3807  0_5%_1  [RSC_060X030X030_2]  198.6 78.93 0 top
R3808  0_5%_1  [RSC_060X030X030_2]  198.6 80.35 0 top
R3809  0_5%_1  [RSC_060X030X030_2]  197.48 81.32 0 top
R3810  0_5%_1  [RSC_060X030X030_2]  195.58 82.74 0 top
R3811  0_5%_1  [RSC_060X030X030_2]  196.39 84.72 90 top
R3813  20K_5%_1  [RSC_060X030X030_2]  195.55 74.74 90 top
R3814  20K_5%_1  [RSC_060X030X030_2]  196.36 81.68 180 top
R3815  20K_5%_1  [RSC_060X030X030_2]  196.39 83.61 90 top
R3816  20K_5%_1  [RSC_060X030X030_2]  198.6 78.32 180 top
R3817  20K_5%_1  [RSC_060X030X030_2]  198.6 79.75 180 top
R3818  20K_5%_1  [RSC_060X030X030_2]  196.62 80.81 270 top
R3819  20K_5%_1  [RSC_060X030X030_2]  195.35 83.61 90 top
R3820  20K_5%_1  [RSC_060X030X030_2]  194.74 84.47 180 top
R3822  0_5%_1  [RSC_060X030X030_2]  196.41 74.51 0 top
R3823  20K_5%_1  [RSC_060X030X030_2]  196.76 71.3 0 top
R3824  short_0805_50  [RSC_200X125X115_2_50_SHORT]  205 74.74 180 bottom
R3825  100K_5%_1  [RSC_060X030X030_2]  192.81 73.98 270 top
R3826  100K_5%_1  [RSC_060X030X030_2]  196.76 73.84 180 top
R3827  short_0805_50  [RSC_200X125X115_2_50_SHORT]  207.56 81.08 0 bottom
R4100  10K_5%_2  [RSC_100X050X040_2]  166.01 10.12 0 top
R4101  10K_5%_2  [RSC_100X050X040_2]  160.73 18.56 90 top
R4103  10K_5%_2  [RSC_100X050X040_2]  161.62 18.56 270 top
R4106  1K_5%_2  [RSC_100X050X040_2]  137.06 13.15 180 top
R4111  24.9_1%_2  [RSC_100X050X035_2]  129.84 42.34 90 top
R4112  2_1%_2  [RSC_100X050X040_2]  128.95 42.34 90 top
R4122  1K_5%_2  [RSC_100X050X040_2]  138.33 12.77 90 top
R4125  10K_5%_2  [RSC_100X050X040_2]  238.66 14.67 90 top
R4126  10K_5%_2  [RSC_100X050X040_2]  239.54 14.67 270 top
R4131  1K_5%_2  [RSC_100X050X040_2]  214.14 12.38 270 top
R4132  1K_5%_2  [RSC_100X050X040_2]  213.26 12.38 90 top
R4136  24.9_1%_2  [RSC_100X050X035_2]  131.09 41.87 0 top
R4200  240_1%_2  [RSC_100X050X040_2]  204.49 12.89 180 top
R4201  240_1%_2  [RSC_100X050X040_2]  128.93 12.89 180 top
R4301  10K_5%_2  [RSC_100X050X040_2]  85.11 32.12 0 bottom
R4302  22_5%_1  [RSC_060X030X030_2]  87.14 34.36 90 bottom
R4303  4.7K_5%_1  [RSC_060X030X030_2]  85.75 33.14 270 bottom
R4350  short_0402_15  [RSC_100X050X040_2_15_SHORT]  231.29 4.13 270 top
R4352  short_0805_50  [RSC_200X125X115_2_50_SHORT]  233.19 4.13 180 top
R4353  1M_5%_1  [RSC_060X030X030_2]  185.21 60.77 90 top
R4354  2.2K_5%_2  [RSC_100X050X040_2]  222.91 7.81 180 top
R4355  2.2K_5%_2  [RSC_100X050X040_2]  224.56 7.81 0 top
R4411  10K_5%_1  [RSC_060X030X030_2]  181.63 114.75 90 bottom
R4412  2.2K_5%_1  [RSC_060X030X030_2]  125.37 85.66 180 bottom
R4413  2.2K_5%_1  [RSC_060X030X030_2]  125.37 85.03 180 bottom
R4414  10K_5%_1  [RSC_060X030X030_2]  125.37 86.43 180 bottom
R4415  33K_1%_2  [RSC_100X050X040_2]  108.1 109.29 270 bottom
R4416  2.2K_5%_1  [RSC_060X030X030_2]  118.51 83.63 270 bottom
R4417  150_1%_2  [RSC_100X050X040_2]  102.38 109.03 270 bottom
R4460  100K_5%_1  [RSC_060X030X030_2]  184.02 65.24 270 top
R4500  short_0402_15  [RSC_100X050X040_2_15_SHORT]  143.81 76.4 180 top
R4501  short_0402_15  [RSC_100X050X040_2_15_SHORT]  113.71 72.57 0 top
R4502  0_5%_2  [RSC_100X050X040_2]  113.71 71.68 0 top
R4503  2_1%_2  [RSC_100X050X040_2]  132.73 42.34 90 top
R4504  10K_5%_1  [RSC_060X030X030_2]  174.8 73.49 90 top
R4505  10K_5%_1  [RSC_060X030X030_2]  173.86 76.34 90 top
R4507  51_5%_2  [RSC_100X050X040_2]  136.95 85.4 270 bottom
R4508  51_5%_2  [RSC_100X050X040_2]  137.84 85.4 270 bottom
R4509  51_5%_2  [RSC_100X050X040_2]  143.81 77.29 180 top
R4510  100K_5%_2  [RSC_100X050X040_2]  218.89 98.06 90 bottom
R4511  short_0201_5  [RSC_060X030X030_2_5_SHORT]  197 47.96 180 top
R4512  100K_5%_1  [RSC_060X030X030_2]  187.09 73.47 180 top
R4513  33_5%_1  [RSC_060X030X030_2]  192.78 62.04 180 top
R4514  1K_1%_1  [RSC_060X030X030_2]  142.41 84.89 0 bottom
R4515  499_1%_2  [RSC_100X050X040_2]  143.42 85.4 270 bottom
R4516  0_5%_1  [RSC_060X030X030_2]  177.95 41.44 0 top
R4517  1K_5%_2  [RSC_100X050X040_2]  142.54 86.79 270 bottom
R4518  121_1%_1  [RSC_060X030X030_2]  166.66 56.78 0 top
R4519  49.9_1%_1  [RSC_060X030X030_2]  149.01 75.46 270 top
R4520  100K_5%_1  [RSC_060X030X030_2]  196.36 52.52 270 top
R4521  0_5%_1  [RSC_060X030X030_2]  171.85 44.24 0 top
R4522  100_1%_1  [RSC_060X030X030_2]  164.57 72.12 270 top
R4523  1K_1%_1  [RSC_060X030X030_2]  133.77 84.56 90 bottom
R4524  100_1%_1  [RSC_060X030X030_2]  163.64 72.11 270 top
R4525  150K_5%_2  [RSC_100X050X040_2]  186.56 42.89 90 top
R4526  51_5%_2  [RSC_100X050X040_2]  113.89 82.31 0 top
R4527  10K_5%_2  [RSC_100X050X040_2]  153.44 76.69 270 top
R4528  100_1%_1  [RSC_060X030X030_2]  130.85 84.64 90 bottom
R4529  100_1%_1  [RSC_060X030X030_2]  131.87 84.64 90 bottom
R4530  100_1%_1  [RSC_060X030X030_2]  167.46 55.67 180 top
R4531  100_1%_1  [RSC_060X030X030_2]  168.58 55.67 0 top
R4532  33_5%_1  [RSC_060X030X030_2]  192.78 62.65 180 top
R4533  100K_5%_1  [RSC_060X030X030_2]  184.43 43.37 180 top
R4534  1K_1%_1  [RSC_060X030X030_2]  134.41 84.56 90 bottom
R4535  10K_5%_1  [RSC_060X030X030_2]  188.64 71.33 180 bottom
R4536  10K_5%_2  [RSC_100X050X040_2]  191.3 62.54 270 bottom
R4537  100K_5%_1  [RSC_060X030X030_2]  196.49 54.29 180 top
R4538  100K_5%_1  [RSC_060X030X030_2]  194.84 72.58 90 bottom
R4539  100K_5%_1  [RSC_060X030X030_2]  214.5 61.91 270 top
R4540  100_1%_1  [RSC_060X030X030_2]  167.51 56.55 270 top
R4541  80.6_1%_1  [RSC_060X030X030_2]  166.4 55.92 270 top
R4542  200K_5%_1  [RSC_060X030X030_2]  188.62 60.26 270 top
R4543  100K_5%_1  [RSC_060X030X030_2]  189.25 60.26 270 top
R4544  24.9_1%_2  [RSC_100X050X035_2]  153.82 71.39 90 top
R4545  1K_5%_1  [RSC_060X030X030_2]  199.16 75.25 180 bottom
R4546  33_5%_1  [RSC_060X030X030_2]  193.04 66.44 0 top
R4547  27,5%  [RSC_060X030X025_2]  187.14 75.31 0 bottom
R4548  27,5%  [RSC_060X030X025_2]  187.14 75.92 0 bottom
R4549  10K_5%_1  [RSC_060X030X030_2]  195.6 47.69 180 top
R4550  4.7K_5%_1  [RSC_060X030X030_2]  184.35 61.03 180 top
R4551  33_5%_1  [RSC_060X030X030_2]  191.77 67.05 0 top
R4552  short_0201_5  [RSC_060X030X030_2_5_SHORT]  197 47.36 180 top
R4553  470_5%_2  [RSC_100X050X040_2]  196.64 12.5 90 top
R4554  100K_5%_2  [RSC_100X050X040_2]  180.24 42.23 270 top
R4555  100K_5%_2  [RSC_100X050X040_2]  189.1 67.96 225 top
R4556  2.2K_5%_1  [RSC_060X030X030_2]  209.19 70.12 0 top
R4557  2.2K_5%_1  [RSC_060X030X030_2]  208.94 69.25 270 top
R4558  1.5K_5%_2  [RSC_100X050X040_2]  141.39 85.4 90 bottom
R4559  100K_5%_2  [RSC_100X050X040_2]  218.59 94.86 90 bottom
R4560  2.2K_5%_1  [RSC_060X030X030_2]  197.38 63.67 0 top
R4561  2.2K_5%_1  [RSC_060X030X030_2]  197.38 63.06 0 top
R4562  100K_5%_1  [RSC_060X030X030_2]  183.16 45.07 180 top
R4563  10K_5%_2  [RSC_100X050X040_2]  198.24 64.71 90 bottom
R4564  100K_5%_2  [RSC_100X050X040_2]  206.27 68.9 270 bottom
R4565  10K_5%_1  [RSC_060X030X030_2]  198.52 50.87 0 top
R4566  49.9_1%_1  [RSC_060X030X030_2]  139.67 77.81 180 top
R4567  4.7_5%_1  [RSC_060X030X030_2]  195.73 43.75 270 top
R4568  4.7_5%_1  [RSC_060X030X030_2]  188.11 42.71 270 top
R4569  4.7_5%_1  [RSC_060X030X030_2]  187.5 42.71 270 top
R4570  4.7_5%_1  [RSC_060X030X030_2]  190.65 43.63 0 top
R4571  100K_5%_1  [RSC_060X030X030_2]  187.72 60.56 270 bottom
R4572  100K_5%_1  [RSC_060X030X030_2]  188.33 60.56 270 bottom
R4573  100K_5%_1  [RSC_060X030X030_2]  189.55 60.51 270 bottom
R4574  100K_5%_1  [RSC_060X030X030_2]  188.94 60.56 270 bottom
R4575  100K_5%_1  [RSC_060X030X030_2]  190.16 60.51 270 bottom
R4576  100K_5%_1  [RSC_060X030X030_2]  190.77 60.56 270 bottom
R4577  100K_5%_1  [RSC_060X030X030_2]  187.11 60.56 270 bottom
R4578  100K_5%_1  [RSC_060X030X030_2]  186.5 60.56 270 bottom
R4579  4.7K_5%_1  [RSC_060X030X030_2]  196.23 49.96 180 top
R4580  short_0201_5  [RSC_060X030X030_2_5_SHORT]  202.28 64.46 270 top
R4582  4.7K_5%_1  [RSC_060X030X030_2]  197.2 49.72 270 top
R4583  short_0603_25  [RSC_160X080X080_2_25_SHORT]  171.09 76.97 180 top
R4584  10K_5%_2  [RSC_100X050X040_2]  106.19 5.91 0 top
R4585  short_0603_25  [RSC_160X080X080_2_25_SHORT]  171.01 70.5 180 top
R4587  49.9_1%_1  [RSC_060X030X030_2]  168.75 60.97 0 top
R4588  49.9_1%_1  [RSC_060X030X030_2]  172.85 63.2 270 top
R4589  51_5%_2  [RSC_100X050X040_2]  145.84 76.68 270 top
R4590  2.2K_5%_1  [RSC_060X030X030_2]  218.28 70.04 270 top
R4591  2.2K_5%_1  [RSC_060X030X030_2]  217.65 70.04 270 top
R4592  4.7_5%_1  [RSC_060X030X030_2]  190.65 42.99 0 top
R4593  100_1%_1  [RSC_060X030X030_2]  154.71 75.25 180 top
R4594  56_5%_2  [RSC_100X050X040_2]  145.33 87.43 90 bottom
R4595  100_1%_2  [RSC_100X050X040_2]  144.31 85.4 90 bottom
R4596  220_1%_2  [RSC_100X050X040_2]  145.33 85.4 90 bottom
R4597  49.9_1%_1  [RSC_060X030X030_2]  135.04 85.14 90 bottom
R4598  100_1%_1  [RSC_060X030X030_2]  154.71 75.88 180 top
R4603  100K_5%_1  [RSC_060X030X030_2]  200.3 47.69 270 top
R4604  49.9_1%_2  [RSC_100X050X040_2]  146.45 85.37 270 bottom
R4605  1K_5%_2  [RSC_100X050X040_2]  161.46 85.4 270 bottom
R4606  330_1%_2  [RSC_100X050X035_2]  233.07 54.8 0 top
R4608  100_1%_1  [RSC_060X030X030_2]  174.75 75.22 270 top
R4609  short_0603_25  [RSC_160X080X080_2_25_SHORT]  182.29 85.27 270 bottom
R4610  short_0603_25  [RSC_160X080X080_2_25_SHORT]  186.71 62.7 180 top
R4611  4.7_5%_1  [RSC_060X030X030_2]  189.58 42.71 270 top
R4612  short_0402_15  [RSC_100X050X040_2_15_SHORT]  114.07 75 90 top
R4613  short_0402_15  [RSC_100X050X040_2_15_SHORT]  114.63 81.42 0 top
R4614  short_0402_15  [RSC_100X050X040_2_15_SHORT]  115.03 79.59 180 top
R4615  short_0402_15  [RSC_100X050X040_2_15_SHORT]  115.03 80.48 0 top
R4619  10K_5%_1  [RSC_060X030X030_2]  204.24 56.96 0 top
R4620  100K_5%_1  [RSC_060X030X030_2]  185.47 59.65 180 top
R4621  100K_5%_1  [RSC_060X030X030_2]  184.6 60.14 90 top
R4622  short_0402_15  [RSC_100X050X040_2_15_SHORT]  201.06 48.1 90 top
R4623  100K_5%_1  [RSC_060X030X030_2]  185.54 43.37 0 top
R4624  100K_5%_1  [RSC_060X030X030_2]  212.75 47.44 180 top
R4625  short_0402_15  [RSC_100X050X040_2_15_SHORT]  107.85 5.78 0 top
R4626  short_0402_15  [RSC_100X050X040_2_15_SHORT]  205.71 71.77 180 bottom
R4628  10K_5%_1  [RSC_060X030X030_2]  181.51 42.74 180 top
R4629  10K_5%_1  [RSC_060X030X030_2]  181.51 41.29 180 top
R4650  10K_5%_1  [RSC_060X030X030_2]  184.68 42.48 90 top
R4678  10K_5%_1  [RSC_060X030X030_2]  190.01 70.55 180 top
R4700  10K_5%_1  [RSC_060X030X030_2]  193.59 65.33 270 bottom
R4702  4.7K_5%_1  [RSC_060X030X030_2]  207.64 70.35 90 top
R4703  100K_5%_1  [RSC_060X030X030_2]  191.08 65.34 270 bottom
R4705  10K_5%_1  [RSC_060X030X030_2]  200.81 53.79 180 top
R4707  10K_5%_1  [RSC_060X030X030_2]  183.16 42.74 180 top
R4708  100K_5%_1  [RSC_060X030X030_2]  184.38 62.85 0 top
R4711  10K_5%_1  [RSC_060X030X030_2]  209.47 61.71 180 top
R4713  20K_5%_1  [RSC_060X030X030_2]  204.62 69.03 180 bottom
R4714  10K_5%_1  [RSC_060X030X030_2]  181.51 40.65 180 top
R4715  10K_5%_1  [RSC_060X030X030_2]  181.51 43.37 180 top
R4717  10K_5%_1  [RSC_060X030X030_2]  196.23 50.6 180 top
R4718  10K_5%_1  [RSC_060X030X030_2]  197.63 54.62 0 top
R4721  10K_5%_1  [RSC_060X030X030_2]  197.13 53.41 0 top
R4722  60.4_1%_2  [RSC_100X050X040_2]  160.57 85.4 90 bottom
R4724  100K_5%_1  [RSC_060X030X030_2]  203.6 72.96 0 bottom
R4725  10K_5%_1  [RSC_060X030X030_2]  205.38 56.96 180 top
R4727  100K_5%_1  [RSC_060X030X030_2]  191.16 70.55 180 top
R4729  200K_5%_1  [RSC_060X030X030_2]  184.05 42.48 90 top
R4733  4.7K_5%_1  [RSC_060X030X030_2]  208.05 69.48 180 top
R4734  10K_5%_1  [RSC_060X030X030_2]  194.81 65.33 270 bottom
R4739  1K_5%_2  [RSC_100X050X040_2]  205.71 70.88 0 bottom
R4742  100K_5%_1  [RSC_060X030X030_2]  202.97 69.03 0 bottom
R4743  100K_5%_1  [RSC_060X030X030_2]  176.68 43.12 270 top
R4744  10K_5%_1  [RSC_060X030X030_2]  180.11 43.37 180 top
R4748  100K_5%_1  [RSC_060X030X030_2]  189.63 72.05 180 bottom
R4749  10K_5%_1  [RSC_060X030X030_2]  187.75 60.21 180 top
R4754  100K_5%_1  [RSC_060X030X030_2]  186.86 74.48 180 bottom
R4756  113_1%_1  [RSC_060X030X026_2]  174.47 76.34 90 top
R4758  100K_5%_2  [RSC_100X050X040_2]  201.06 73.98 90 bottom
R4759  100K_5%_2  [RSC_100X050X040_2]  200.45 72.38 90 bottom
R4761  100K_5%_1  [RSC_060X030X030_2]  202.89 64.45 270 top
R4762  100K_5%_1  [RSC_060X030X030_2]  184.76 65.24 90 top
R4763  100K_5%_1  [RSC_060X030X030_2]  207.69 62.93 180 bottom
R4765  10K_5%_1  [RSC_060X030X030_2]  213.89 61.91 270 top
R4766  100K_5%_1  [RSC_060X030X030_2]  190.47 65.34 270 bottom
R4768  100K_5%_1  [RSC_060X030X030_2]  188.69 71.41 180 top
R4769  10K_5%_1  [RSC_060X030X030_2]  205.25 55.95 180 top
R4771  100K_5%_1  [RSC_060X030X030_2]  190.4 71.69 0 top
R4772  100K_5%_1  [RSC_060X030X030_2]  188.69 72.02 180 top
R4774  100K_5%_1  [RSC_060X030X030_2]  203.1 55.95 0 top
R4782  1M_5%_1  [RSC_060X030X030_2]  199.67 76.14 180 bottom
R4786  2.2K_5%_1  [RSC_060X030X030_2]  214.02 74.49 90 top
R4787  2.2K_5%_1  [RSC_060X030X030_2]  214.02 73.34 270 top
R4790  22_5%_1  [RSC_060X030X030_2]  217.7 47.94 270 top
R4792  2.2K_5%_1  [RSC_060X030X030_2]  217.95 39.18 270 top
R4793  22_5%_1  [RSC_060X030X030_2]  221.54 47.94 270 top
R4794  22_5%_1  [RSC_060X030X030_2]  216.76 47.94 270 top
R4795  22_5%_1  [RSC_060X030X030_2]  220.85 47.94 270 top
R4796  22_5%_1  [RSC_060X030X030_2]  225.24 47.94 270 top
R4797  499_1%_1  [RSC_060X030X030_2]  213.26 70.68 180 top
R4798  10K_5%_1  [RSC_060X030X030_2]  199.06 61.28 0 top
R4800  short_0402_15  [RSC_100X050X040_2_15_SHORT]  107.08 106.24 270 bottom
R4802  2.2K_5%_1  [RSC_060X030X030_2]  198.65 64.84 180 top
R4803  100K_5%_1  [RSC_060X030X030_2]  184.43 66.11 0 top
R4804  100K_5%_1  [RSC_060X030X030_2]  204.34 65.01 270 top
R4805  100K_5%_1  [RSC_060X030X030_2]  186.1 66.16 90 top
R4806  100K_5%_2  [RSC_100X050X040_2]  172.08 61.37 180 top
R4807  100_5%_2  [RSC_100X050X040_2]  139.61 85.4 90 bottom
R4808  short_0201_5  [RSC_060X030X030_2_5_SHORT]  195.35 42.84 0 top
R4809  100K_5%_1  [RSC_060X030X030_2]  202.46 72.96 180 bottom
R4811  100K_5%_1  [RSC_060X030X030_2]  194.21 72.58 90 bottom
R4812  200_1%_1  [RSC_060X030X030_2]  185.37 66.16 270 top
R4816  10K_5%_2  [RSC_100X050X040_2]  187.01 73.33 180 bottom
R4819  200_1%_1  [RSC_060X030X030_2]  191.16 59.5 0 top
R4821  short_0402_15  [RSC_100X050X040_2_15_SHORT]  103.88 58.59 0 bottom
R4822  1K_5%_2  [RSC_100X050X040_2]  125.32 70.32 180 top
R4823  0_5%_2  [RSC_100X050X040_2]  125.5 59.37 90 top
R4825  2.2K_5%_1  [RSC_060X030X030_2]  200.58 63.54 0 top
R4827  2.2K_5%_1  [RSC_060X030X030_2]  188.64 70.11 180 bottom
R4828  2.2K_5%_1  [RSC_060X030X030_2]  220.8 37.91 0 top
R4830  2.2K_5%_1  [RSC_060X030X030_2]  217.62 38.27 0 top
R4831  10K_5%_1  [RSC_060X030X030_2]  191.69 65.34 270 bottom
R4832  1K_5%_1  [RSC_060X030X030_2]  211.62 8.31 270 top
R4834  27K_5%_1  [RSC_060X030X030_2]  223.08 53.05 270 bottom
R4835  1M_5%_2  [RSC_100X050X040_2]  216.94 51.93 0 top
R4837  10K_5%_1  [RSC_060X030X030_2]  172.73 59.84 270 top
R4839  10K_5%_1  [RSC_060X030X030_2]  194.21 65.33 270 bottom
R4842  100K_5%_2  [RSC_100X050X040_2]  194.92 43.96 270 top
R4845  27K_5%_1  [RSC_060X030X030_2]  223.69 53.05 270 bottom
R4846  15_5%_1  [RSC_060X030X030_2]  173.61 57.21 270 top
R4847  15_5%_1  [RSC_060X030X030_2]  173 57.21 270 top
R4848  15_5%_1  [RSC_060X030X030_2]  173.1 56.09 270 top
R4849  15_5%_1  [RSC_060X030X030_2]  172.49 55.82 270 top
R4850  33_5%_1  [RSC_060X030X030_2]  171.6 55.43 270 top
R4851  100K_5%_2  [RSC_100X050X040_2]  172.11 42.58 0 top
R4854  2.2K_5%_1  [RSC_060X030X030_2]  177.7 84.65 270 bottom
R4855  short_0402_15  [RSC_100X050X040_2_15_SHORT]  105.56 93.92 180 top
R4856  2.2K_5%_1  [RSC_060X030X030_2]  188.64 70.72 180 bottom
R4858  100K_5%_2  [RSC_100X050X040_2]  172.11 41.7 0 top
R4859  100K_5%_2  [RSC_100X050X040_2]  195.86 49.09 0 top
R4860  100K_5%_2  [RSC_100X050X040_2]  177.95 43.09 0 top
R4861  1K_5%_1  [RSC_060X030X030_2]  250.42 42.33 180 top
R4862  10M_5%_1  [RSC_060X030X030_2]  204.7 50.2 90 bottom
R4863  100K_5%_2  [RSC_100X050X040_2]  172.11 43.47 0 top
R4864  100K_5%_2  [RSC_100X050X040_2]  177.95 42.2 0 top
R4865  49.9K_1%_1  [RSC_060X030X030_2]  264.56 33.85 270 bottom
R4866  49.9K_1%_1  [RSC_060X030X030_2]  265.2 33.85 270 bottom
R4869  33_5%_1  [RSC_060X030X030_2]  39.39 34.48 0 bottom
R4870  2.2K_5%_1  [RSC_060X030X030_2]  178.33 84.65 270 bottom
R4884  499_1%_1  [RSC_060X030X030_2]  214.02 71.82 270 top
